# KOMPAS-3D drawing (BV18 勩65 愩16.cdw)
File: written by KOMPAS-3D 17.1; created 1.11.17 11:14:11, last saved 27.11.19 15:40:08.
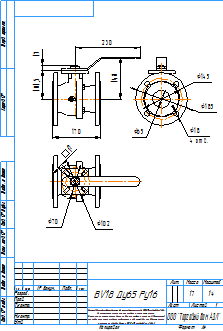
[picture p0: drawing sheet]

Sheet 1: A4, portrait

Title block, sheet 1: name: BV18 Ду65 Ру16; mass: 17; sheets: 1; sheet format: A4; stored path: C:\Users\kka\KOMPAS_Work\!Trash\BV18\KOMPAS 2D\BV18 Ду50 Ру40.cdw

Views: Проекционный вид 4, Проекционный вид 5
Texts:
  kka
  adl
  Рама для чертежей
  Лит-Масса-Масштаб
  Материал-Предприятие
  Масштаб
  Изм.
  Лист
  № докум.
  Подп.
  Дата
  Лит.
  Разраб.
  Пров.
  Т.контр.
  Листов
  Внимание! Данный продукт является объектом авторского права ООО «Торговый Дом АДЛ».
  Запрещается изменение, копирование, распространение
  (в том числе путем копирования на другие сайты и ресурсы в Интернете)
  или любое иное использование информации и объектов без предварительного
  согласия правообладателя (ООО «Торговый Дом АДЛ»).
  Н.контр.
  Утв.
  ООО "Торговый дом АДЛ"
  Изменение
  Номер документа
  Подпись
  Обозначение документа
  Наименование изделия
  Масса изделия по ГОСТ 2.109-73
  Порядковый номер листа
  Общее количество листов в документе
  Характер работы, выполненной лицом, подписавшим документ
  Наименование или индекс предприятия, выпускающего документ
  Инв. № подл.
  Подп. и дата
  Взам. инв. №
  Инв. № дубл.
  Инвентарный номер подлинника по ГОСТ 2.501-68
  Подпись принявшего подлинник в отдел технической документации
  Инвентарный номер подлинника, взамен которого выпущен данный подлинник
  Инвентарный номер дубликата по ГОСТ 2.502-68
  Подпись принявшего дубликат в отдел технической документации
  Справ. №
  Перв. примен.
  Обозначение документа, взамен или на основании которого выпущен данный документ
  Обозначение документа, в котором впервые записан данный документ
  Подпись лица, копировавшего чертеж
  Обозначение формата листа
  !Рама для чертежа
Dimensions and other numbers on the sheet: 170; 101,5; 17; 230; 148; 145; 18; 4 отв.; 65; 185; 1:4; 1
